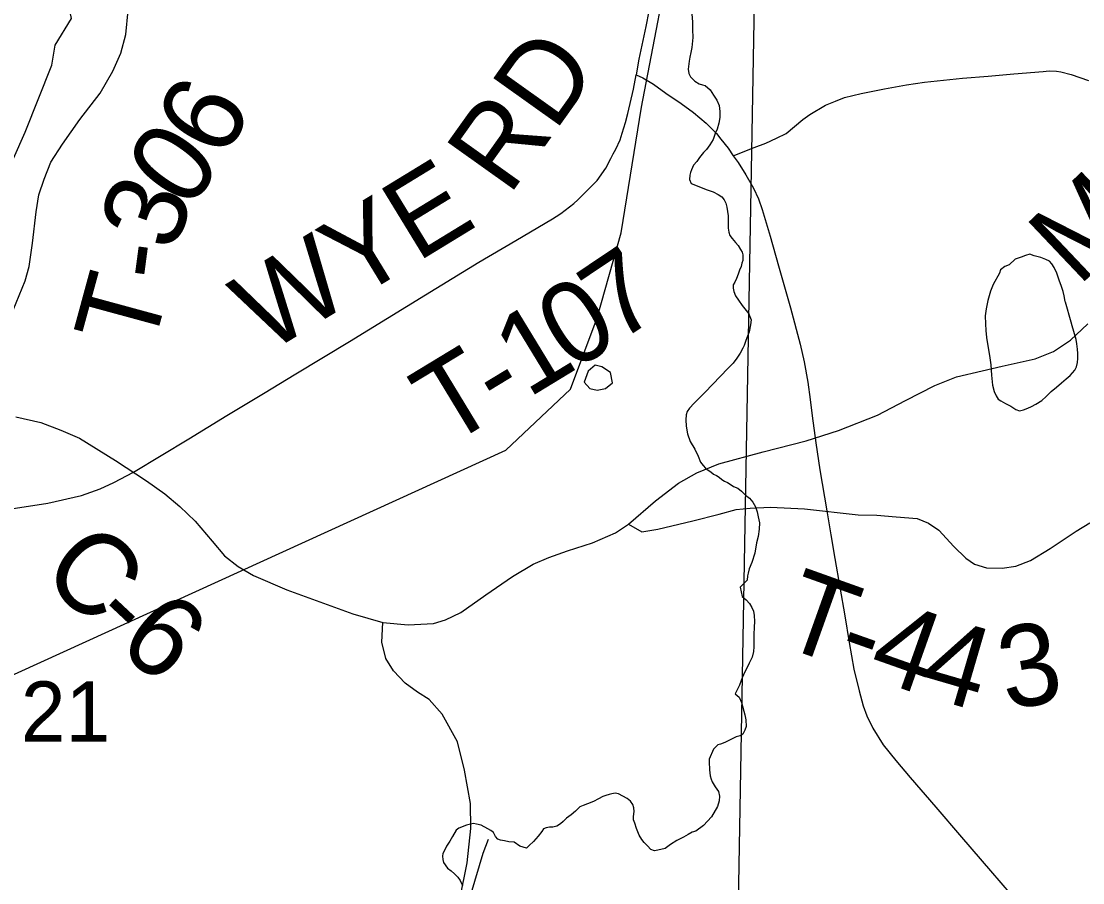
# Model space of a CAD drawing. Extents: x -6.1 to 38, y -7.7 to 22.
# Drawn here: x 2.73 to 3.47, y 15.333 to 15.933 of the extents above; entities that cross this region are included whole.
import ezdxf

# ---------------------------------------------------------------- set-up
doc = ezdxf.new("R2010")
doc.units = 0
for name, color, linetype in [('GM_X_Corporation', 7, 'Continuous'), ('GM_X_County_Road', 7, 'Continuous'), ('GM_X_County_Road_Text', 7, 'Continuous'), ('GM_X_Major_River', 7, 'Continuous'), ('GM_X_Minor_Lake', 7, 'Continuous'), ('GM_X_Minor_River', 7, 'Continuous'), ('GM_X_Rail_Line', 7, 'Continuous'), ('GM_X_Section_Text', 7, 'Continuous'), ('GM_X_Township_Road', 7, 'Continuous'), ('GM_X_Township_Road_Text', 7, 'Continuous')]:
    doc.layers.add(name, color=color, linetype=linetype)

msp = doc.modelspace()

# ---------------------------------------------------------------- linework, layer by layer
at = {"layer": 'GM_X_Corporation'}
msp.add_lwpolyline([(2.23638, 16.06946), (3.24267, 16.03673), (3.24072, 15.94663), (3.23485, 15.60898), (3.22944, 15.30622), (3.22502, 15.03923), (2.22108, 15.06099)], close=True, dxfattribs=at)
at = {"layer": 'GM_X_County_Road'}
for points in [[(3.16949, 15.95137), (3.16533, 15.92985), (3.16056, 15.90713), (3.15859, 15.89614), (3.16318, 15.8941), (3.17072, 15.88957), (3.17925, 15.88341), (3.19001, 15.87619), (3.19862, 15.86988), (3.20746, 15.86242), (3.21453, 15.85535), (3.21768, 15.85143), (3.22261, 15.84498), (3.22631, 15.83979), (3.2296, 15.83506), (3.23491, 15.82645), (3.24045, 15.8173), (3.24383, 15.80984), (3.24636, 15.80238), (3.25205, 15.78378), (3.25366, 15.77796)], [(3.25366, 15.77796), (3.2582, 15.76148), (3.2662, 15.73388), (3.27289, 15.70859), (3.27565, 15.69621), (3.27819, 15.68207), (3.2798, 15.67007), (3.28119, 15.65854), (3.28384, 15.63982), (3.2865, 15.6211), (3.29142, 15.59243), (3.29418, 15.57582), (3.29695, 15.55921), (3.30041, 15.53923), (3.30387, 15.51924), (3.3071, 15.50068), (3.31032, 15.48211), (3.31386, 15.46711), (3.31671, 15.45658), (3.31932, 15.44974), (3.3234, 15.44113), (3.33077, 15.42952), (3.33939, 15.41853), (3.34938, 15.40677), (3.36729, 15.38601), (3.38521, 15.36525), (3.40551, 15.34173), (3.41988, 15.32508)], [(2.72668, 15.6579), (2.74396, 15.65406), (2.75803, 15.64873), (2.77104, 15.64297), (2.79599, 15.62762), (2.81753, 15.61333), (2.83032, 15.60437), (2.84077, 15.59541), (2.85144, 15.58518), (2.86338, 15.57132), (2.8719, 15.56108), (2.88138, 15.55361), (2.89204, 15.54746), (2.91525, 15.53751), (2.96143, 15.52069), (2.98227, 15.51478), (2.99989, 15.51297), (3.01754, 15.51405), (3.02585, 15.51643), (3.03651, 15.52164), (3.05403, 15.53396), (3.07251, 15.54675), (3.08695, 15.55527), (3.09785, 15.56001), (3.11087, 15.56451), (3.12816, 15.5702), (3.14427, 15.57706), (3.15327, 15.58322), (3.17221, 15.59933), (3.18808, 15.61164), (3.20087, 15.61898), (3.21627, 15.62514), (3.24706, 15.63343), (3.27713, 15.64124), (3.29963, 15.64835), (3.32663, 15.65901), (3.34629, 15.66919), (3.36666, 15.67985), (3.38181, 15.68577), (3.39958, 15.69003), (3.41355, 15.69311), (3.43652, 15.69832), (3.44931, 15.70353), (3.46116, 15.71135), (3.47323, 15.72272)]]:
    msp.add_lwpolyline(points, dxfattribs=at)
at = {"layer": 'GM_X_Major_River'}
for points in [[(3.19747, 15.93843), (3.19791, 15.93312), (3.19797, 15.92779), (3.19804, 15.92209), (3.19735, 15.91524)], [(3.19735, 15.91524), (3.19663, 15.91181), (3.19591, 15.90838), (3.19556, 15.90572), (3.19521, 15.90381), (3.19487, 15.90001), (3.19529, 15.89697), (3.19645, 15.8947), (3.19953, 15.89169), (3.20259, 15.88982), (3.20488, 15.88908), (3.20679, 15.88872), (3.21024, 15.88571), (3.21257, 15.88193), (3.21489, 15.87853), (3.21645, 15.87475), (3.21688, 15.87057), (3.21693, 15.86639), (3.21621, 15.86258), (3.21512, 15.85839), (3.21364, 15.85533), (3.21216, 15.85113), (3.20993, 15.84731), (3.20768, 15.84425), (3.20543, 15.84194), (3.2028, 15.83849), (3.20093, 15.83581), (3.19868, 15.83313), (3.1972, 15.83007), (3.19646, 15.82816), (3.19611, 15.82626), (3.19576, 15.82322), (3.19693, 15.82056), (3.20801, 15.81611), (3.21221, 15.81463), (3.21565, 15.81277), (3.21833, 15.81127), (3.21987, 15.80901), (3.22104, 15.80674), (3.22183, 15.80408), (3.22225, 15.80105), (3.22266, 15.79801), (3.22272, 15.79307), (3.22276, 15.78927), (3.22317, 15.78661), (3.22396, 15.78433), (3.22551, 15.78207), (3.22782, 15.77943), (3.22975, 15.77717), (3.2313, 15.77452), (3.23246, 15.77263), (3.23286, 15.77074), (3.23288, 15.76883), (3.23291, 15.76693), (3.23217, 15.76503), (3.23181, 15.76274), (3.23071, 15.76007), (3.2296, 15.7574), (3.22849, 15.75434), (3.22738, 15.75167), (3.22626, 15.74976), (3.22629, 15.74748), (3.2267, 15.7452), (3.22787, 15.74217), (3.22981, 15.73915), (3.23251, 15.73537), (3.23444, 15.73311), (3.23714, 15.72972), (3.23792, 15.72782), (3.23871, 15.72555), (3.23837, 15.72212), (3.23729, 15.71717), (3.23581, 15.71297), (3.2347, 15.7103), (3.23397, 15.70763), (3.23286, 15.70572), (3.231, 15.70228), (3.22875, 15.69884), (3.22613, 15.69539), (3.22238, 15.69155), (3.2066, 15.67504), (3.20247, 15.67082), (3.19909, 15.66737), (3.1957, 15.66391), (3.19421, 15.66161), (3.19348, 15.65932), (3.19314, 15.6559), (3.19357, 15.65134), (3.19439, 15.64603), (3.19635, 15.64072), (3.19946, 15.63543), (3.20179, 15.63051), (3.20336, 15.62634), (3.20529, 15.62408), (3.20683, 15.6222), (3.20875, 15.6207), (3.21066, 15.61958), (3.21258, 15.61807), (3.2145, 15.61695), (3.21641, 15.61583), (3.21833, 15.61433)], [(3.21833, 15.61433), (3.22024, 15.61321), (3.22215, 15.61208), (3.22407, 15.61096), (3.22637, 15.60946), (3.22942, 15.60835), (3.23211, 15.6061), (3.2348, 15.60347), (3.23749, 15.60121), (3.2398, 15.59857), (3.24174, 15.59517), (3.24292, 15.59176), (3.24372, 15.58835), (3.24453, 15.58417), (3.2442, 15.57961), (3.2435, 15.57465), (3.24241, 15.57008), (3.24135, 15.56285), (3.23915, 15.55636), (3.23729, 15.55216), (3.23657, 15.54911), (3.23621, 15.54721), (3.23587, 15.54416), (3.23324, 15.54147), (3.23098, 15.53917), (3.23258, 15.53272), (3.23527, 15.53047), (3.23758, 15.52783), (3.23913, 15.52519), (3.2403, 15.52254), (3.24072, 15.5195), (3.24114, 15.51532), (3.24081, 15.51152), (3.24049, 15.50619), (3.24054, 15.50163), (3.24059, 15.49783), (3.24025, 15.4944), (3.23953, 15.49059), (3.23841, 15.48868), (3.2373, 15.48639), (3.23619, 15.48372), (3.23433, 15.48027), (3.23247, 15.47607), (3.23063, 15.47111), (3.22878, 15.46729), (3.22766, 15.465), (3.23035, 15.46275), (3.23191, 15.45896), (3.23429, 15.45024), (3.23509, 15.44682), (3.23515, 15.44226), (3.23442, 15.43959), (3.23293, 15.43692), (3.23104, 15.43576), (3.22839, 15.43497), (3.22498, 15.43342), (3.22272, 15.43225), (3.22045, 15.43109), (3.21742, 15.42992), (3.21553, 15.42952), (3.21252, 15.42645), (3.20956, 15.41958), (3.2096, 15.41577), (3.20963, 15.41387), (3.20965, 15.41197), (3.21007, 15.40779), (3.21086, 15.40552), (3.21165, 15.40363), (3.21358, 15.40022), (3.2159, 15.39683), (3.2167, 15.39379), (3.21636, 15.39037), (3.21526, 15.38655), (3.21117, 15.37929), (3.20554, 15.37315), (3.20026, 15.3693), (3.19761, 15.36851), (3.19496, 15.36696), (3.19156, 15.36503), (3.18703, 15.3627), (3.1825, 15.35999), (3.17873, 15.35729), (3.1738, 15.35611), (3.17152, 15.3557), (3.16885, 15.35644), (3.16654, 15.35908), (3.16424, 15.36133), (3.16269, 15.3636), (3.16075, 15.36662), (3.1588, 15.37116), (3.15761, 15.37496), (3.15683, 15.37723), (3.1568, 15.37951), (3.15714, 15.38294), (3.15711, 15.38559), (3.15632, 15.38787), (3.15478, 15.39014), (3.15247, 15.39201), (3.14636, 15.39537), (3.14407, 15.39573), (3.14179, 15.39533)], [(3.14179, 15.39533), (3.1399, 15.39493), (3.13762, 15.39415), (3.13535, 15.39337), (3.13233, 15.39181), (3.12893, 15.38988), (3.12477, 15.38832), (3.12174, 15.38715), (3.11947, 15.38636), (3.11646, 15.38329), (3.11345, 15.3806), (3.11006, 15.37829), (3.1078, 15.37598), (3.10592, 15.37444), (3.10328, 15.3729), (3.10063, 15.37211), (3.09834, 15.37208), (3.09607, 15.37168), (3.09418, 15.3709), (3.09306, 15.36899), (3.09043, 15.36592), (3.08706, 15.36209), (3.08405, 15.3594), (3.08217, 15.35748), (3.07759, 15.35895), (3.07376, 15.36157), (3.06995, 15.36192), (3.0669, 15.36265), (3.06424, 15.363), (3.06233, 15.36374), (3.06078, 15.36563), (3.05923, 15.36827), (3.05732, 15.36978), (3.0554, 15.3709), (3.05081, 15.37351), (3.04738, 15.37424), (3.04547, 15.3746), (3.0432, 15.3742), (3.04054, 15.37341), (3.03525, 15.37146), (3.03336, 15.36992), (3.03075, 15.36571), (3.02889, 15.36227), (3.02665, 15.35883), (3.02516, 15.35577), (3.02404, 15.35386), (3.02369, 15.35195), (3.02409, 15.34968), (3.0245, 15.3474), (3.02721, 15.34362), (3.02989, 15.34175), (3.03219, 15.33949), (3.0345, 15.33723), (3.03605, 15.33497), (3.03761, 15.33156)]]:
    msp.add_lwpolyline(points, dxfattribs=at)
at = {"layer": 'GM_X_Minor_Lake'}
msp.add_line((3.12629, 15.67759), (3.13158, 15.67643), dxfattribs=at)
for points in [[(3.45766, 15.73781), (3.45753, 15.73837), (3.45672, 15.74217), (3.45593, 15.7452), (3.45475, 15.74861), (3.45318, 15.75316), (3.4516, 15.75808), (3.44965, 15.76187), (3.4481, 15.76451), (3.44656, 15.7664), (3.44388, 15.76751), (3.44045, 15.769), (3.43587, 15.77009), (3.43282, 15.7712), (3.42979, 15.77041), (3.42676, 15.76924), (3.42259, 15.76768), (3.41846, 15.76384), (3.41543, 15.76267), (3.41241, 15.76035), (3.41168, 15.75807)], [(3.41168, 15.75807), (3.40721, 15.75004), (3.40536, 15.74546), (3.40354, 15.73897), (3.40247, 15.73326), (3.40176, 15.72831), (3.40183, 15.72261), (3.40226, 15.71805), (3.4027, 15.71311), (3.40352, 15.70742), (3.40475, 15.70059), (3.40558, 15.69413), (3.40604, 15.68691), (3.40688, 15.68008), (3.40807, 15.67553), (3.40925, 15.6725), (3.4108, 15.67023), (3.41271, 15.66911), (3.41577, 15.66724), (3.4196, 15.66538), (3.42304, 15.66313), (3.42572, 15.66201), (3.42837, 15.6628), (3.4314, 15.66397), (3.43405, 15.66514), (3.43707, 15.66669), (3.44122, 15.66939), (3.44423, 15.67208), (3.44761, 15.67554), (3.45138, 15.67862), (3.45476, 15.68169), (3.45815, 15.68439), (3.46079, 15.6867), (3.46417, 15.69053), (3.46528, 15.69282), (3.466, 15.69587), (3.46635, 15.69854), (3.46631, 15.70196), (3.4659, 15.705), (3.46547, 15.70879), (3.46506, 15.71183), (3.46229, 15.72131), (3.4615, 15.72396), (3.45766, 15.73781)], [(3.13158, 15.67643), (3.13726, 15.67755), (3.14218, 15.68171), (3.14069, 15.68892), (3.13465, 15.69273), (3.13012, 15.69388), (3.12519, 15.68972), (3.12252, 15.68215), (3.12629, 15.67759)]]:
    msp.add_lwpolyline(points, dxfattribs=at)
at = {"layer": 'GM_X_Minor_River'}
for points in [[(2.7103, 15.80548), (2.73313, 15.85622), (2.75178, 15.9028), (2.75409, 15.91682), (2.76548, 15.93536), (2.76287, 15.94751), (2.75798, 15.95814), (2.75806, 15.98885), (2.75737, 16.01122), (2.74871, 16.02452), (2.74382, 16.03667), (2.7431, 16.05032), (2.74804, 16.05827), (2.74844, 16.06547), (2.74958, 16.06774), (2.75111, 16.07646), (2.74666, 16.10605), (2.7464, 16.14965), (2.74533, 16.1762), (2.73629, 16.19063), (2.73027, 16.20051), (2.73072, 16.22515), (2.72735, 16.23805)], [(3.04367, 15.32597), (3.05206, 15.354), (3.05587, 15.36385)]]:
    msp.add_lwpolyline(points, dxfattribs=at)
at = {"layer": 'GM_X_Rail_Line'}
msp.add_lwpolyline([(2.51223, 15.38149), (3.06782, 15.63481), (3.11291, 15.67727), (3.13148, 15.7268), (3.14828, 15.78607), (3.16243, 15.87364), (3.18631, 15.99837), (3.21903, 16.07267), (3.23555, 16.09193), (3.34813, 16.1859), (3.37289, 16.22836), (3.40207, 16.30266), (3.44717, 16.39554), (3.5073, 16.49992)], dxfattribs=at)
at = {"layer": 'GM_X_Township_Road'}
for points in [[(2.72476, 15.73232), (2.73308, 15.75258), (2.73586, 15.7626), (2.7382, 15.77881), (2.74076, 15.80078), (2.74268, 15.8125), (2.7463, 15.82359), (2.75099, 15.83532), (2.75912, 15.84795), (2.77111, 15.86494), (2.78543, 15.88327), (2.7941, 15.8986), (2.79983, 15.91124), (2.80324, 15.92425), (2.80495, 15.94088), (2.80409, 15.96711), (2.80153, 15.99356), (2.80068, 16.01338), (2.80025, 16.04345), (2.79983, 16.06542), (2.79961, 16.08013), (2.80239, 16.10572), (2.80448, 16.13366)], [(2.72045, 15.59328), (2.74894, 15.59784), (2.77244, 15.60305), (2.78526, 15.60786), (2.79495, 15.61208), (2.80851, 15.61944), (2.82781, 15.63104), (2.84712, 15.64265), (2.87368, 15.65876), (2.90024, 15.67488), (2.92055, 15.68721), (2.94085, 15.69953), (2.95892, 15.7105), (2.98542, 15.72671), (3.01192, 15.74292), (3.03055, 15.75432), (3.04918, 15.76571), (3.07478, 15.78077), (3.10039, 15.79583), (3.10304, 15.79752), (3.10622, 15.79962), (3.1093, 15.80183), (3.11228, 15.80417), (3.11522, 15.80659), (3.11802, 15.80912), (3.12077, 15.81175), (3.13144, 15.82259), (3.13745, 15.83114), (3.14111, 15.8379), (3.14262, 15.84109), (3.1444, 15.84429), (3.1475, 15.85095), (3.149, 15.85546), (3.15126, 15.86288), (3.15286, 15.86918), (3.15685, 15.88625), (3.15859, 15.89614)], [(3.22631, 15.83979), (3.24072, 15.84542), (3.24895, 15.84844), (3.25632, 15.85204), (3.26316, 15.85538), (3.27475, 15.86513), (3.27955, 15.8685), (3.29058, 15.87499), (3.29752, 15.87792), (3.30369, 15.88025), (3.3153, 15.88314), (3.33164, 15.88632), (3.3469, 15.88922), (3.35951, 15.89114), (3.38591, 15.8938), (3.40374, 15.89532), (3.42156, 15.89683), (3.44214, 15.89849), (3.44619, 15.89882), (3.45147, 15.89859), (3.4543, 15.89828), (3.46163, 15.89638), (3.47361, 15.89221)], [(3.15327, 15.58322), (3.16251, 15.57777), (3.17364, 15.57967), (3.19803, 15.58559), (3.2165, 15.59009), (3.22835, 15.59341), (3.23805, 15.59435), (3.25226, 15.59506), (3.27595, 15.59388), (3.31337, 15.58962), (3.32616, 15.58938), (3.33966, 15.58819), (3.35434, 15.58701), (3.36216, 15.58393), (3.3695, 15.57896), (3.37992, 15.56759), (3.38821, 15.55953), (3.39436, 15.55527), (3.40265, 15.55267), (3.41355, 15.55243), (3.42302, 15.55386), (3.43321, 15.55788), (3.44695, 15.56617), (3.46518, 15.57824), (3.47469, 15.58404)], [(3.0358, 15.32199), (3.04101, 15.34733), (3.04361, 15.37125), (3.04338, 15.38854), (3.03912, 15.41175), (3.03414, 15.43164), (3.02359, 15.45086), (3.01448, 15.46094), (3.00633, 15.46622), (2.99766, 15.47238), (2.98962, 15.48091), (2.9844, 15.48967), (2.98156, 15.50104), (2.98227, 15.51478)]]:
    msp.add_lwpolyline(points, dxfattribs=at)

# ---------------------------------------------------------------- texts
at = {"layer": 'GM_X_County_Road_Text'}
for s, rotation, p in [('M', 43.46267, (3.46652, 15.74814)), ('C', 316.61467, (2.74227, 15.54757)), ('-', 316.87188, (2.77639, 15.51532)), ('6', 319.66264, (2.79568, 15.49736))]:
    msp.add_text(s, height=0.05682, rotation=rotation, dxfattribs=at).set_placement(p)
at = {"layer": 'GM_X_Section_Text'}
msp.add_text('21', height=0.041856, rotation=0.00001, dxfattribs=at).set_placement((2.73011, 15.43174))
at = {"layer": 'GM_X_Township_Road_Text'}
for s, height, rotation, p in [('RD', 0.056818, 54.52153, (3.07, 15.8111)), ('6', 0.05682, 61.54496, (2.87155, 15.83594)), ('0', 0.05682, 53.88156, (2.8465, 15.80067)), ('WYE', 0.056818, 31.42891, (2.90154, 15.70136)), ('3', 0.05682, 69.99154, (2.83651, 15.7715)), ('7', 0.05682, 33.87815, (3.14522, 15.70856)), ('-', 0.05682, 82.42128, (2.8342, 15.75153)), ('T', 0.05682, 74.79224, (2.82143, 15.70243)), ('0', 0.05682, 31.62547, (3.11337, 15.68889)), ('1', 0.05682, 31.33083, (3.0832, 15.67052)), ('T', 0.05682, 31.24672, (3.02684, 15.63632)), ('-', 0.05682, 31.26609, (3.06319, 15.65837)), ('T', 0.05682, 340.34935, (3.25611, 15.49975)), ('4', 0.05682, 340.51386, (3.31828, 15.47756)), ('4', 0.05682, 343.7157, (3.35457, 15.46482)), ('3', 0.05682, 10.15449, (3.41646, 15.45349)), ('-', 0.05682, 340.37358, (3.29616, 15.48545))]:
    msp.add_text(s, height=height, rotation=rotation, dxfattribs=at).set_placement(p)

doc.saveas('drawing.dxf')
